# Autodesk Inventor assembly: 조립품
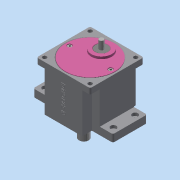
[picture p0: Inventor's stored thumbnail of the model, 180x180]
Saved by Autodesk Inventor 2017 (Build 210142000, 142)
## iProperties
Part Number: 조립품
Material: 일반
Document SubType Name: Assembly
Designer: user
Author: user
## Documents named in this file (10)
- C:\Users\user\Desktop\700116V1004\조립품.iam
- C:\Users\user\Desktop\700116V1004\메인 축.ipt
- C:\Users\user\Desktop\700116V1004\베어링 608.ipt
- C:\Users\user\Desktop\700116V1004\베어링 6003.ipt
- C:\Users\user\Desktop\700116V1004\본체.ipt
- C:\Users\user\Desktop\700116V1004\볼트 M4.ipt
- C:\Users\user\Desktop\700116V1004\서브 축.ipt
- C:\Users\user\Desktop\700116V1004\오일 실 8 22 7.ipt
- C:\Users\user\Desktop\700116V1004\오일 실 17 32 8.ipt
- C:\Users\user\Desktop\700116V1004\커버.ipt
